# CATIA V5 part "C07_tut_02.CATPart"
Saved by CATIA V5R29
Part number: Part1
Bounding box of the stored display mesh (mm): x 0 to 32, y -32 to 32, z -15 to 36
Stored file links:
  D:\Abhinav\2019\3rd Session\CATIA V5 2019\RESOURCES\CATIA_RESOURCES\Tutorial Files\Tutorials\Tutorials\c07_catia_v5_6r2018_tut\c07_catia_v5_6r2018_tut\c07_catia_v5_6r2018_tut\C07_tut_02.CATPart
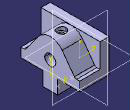
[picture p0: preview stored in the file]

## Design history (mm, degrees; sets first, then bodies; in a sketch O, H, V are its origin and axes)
Body1 (main body)
  Sketch1 on zx-plane, origin (0, 0, 0), H (-1, 0, 0), V (0, 0, 1)
    point P1 (0, 36)
    line L1 (0, 36) -> (0, 0)
    line L2 (0, 0) -> (-32, 0)
    line L3 (0, 36) -> (-10, 36)
    line L4 (-10, 36) -> (-10, 10)
    line L5 (-10, 10) -> (-32, 10)
    line L6 (-32, 10) -> (-32, 0)
    length L2 = 32
    length L3 = 10
    length L6 = 10
    distance L3 L2 = 36
    coincidence: P1 V
    vertical: L1 V, L4 V, L6 V
    horizontal: L2 H, L3 H, L5 H
  Pad1: profile Sketch1, direction (0, 1, 0), length 32, mirrored extent
  Sketch2 on face of Pad1 from Sketch1.L6, origin (32, 0, 0), H (0, 1, 0), V (0, 0, 1)
    arc A1 centre (0, 20) radius 16 from (12.9443, 29.4046) to (-12.9443, 29.4046) ccw
    point P1 (0, 20)
    reference projected line E1 (-32, 36) -> (32, 36) from edge [face of Pad1 from Sketch1.L4 | face of Pad1 from Sketch1.L3]
    line L1 (-27.0425, 10) -> (27.0425, 10)
    point P2 (-27.0425, 10)
    point P3 (27.0425, 10)
    reference projected line E2 (-32, 10) -> (32, 10) from edge [face of Pad1 from Sketch1.L6 | face of Pad1 from Sketch1.L5]
    line L2 (-27.0425, 10) -> (-12.9443, 29.4046)
    line L3 (27.0425, 10) -> (12.9443, 29.4046)
    radius A1 = 16
    angle L3 L2 = 72
    coincidence: P1 V, L1 E2
    tangency: A1 E1, L2 A1, L3 A1
    horizontal: L1 H
    symmetry: P3 P2 V
  Pad2: profile Sketch2, direction (1, 0, 0), up to the existing solid (limit type 2)
  Sketch3 on face of Pad2, origin (32, 0, 0), H (0, 1, 0), V (0, 0, 1)
    line L1 (-8, 0) -> (8, 0)
    line L2 (8, 0) -> (8, -15)
    line L3 (8, -15) -> (-8, -15)
    line L4 (-8, -15) -> (-8, 0)
    reference projected line E1 (-32, 0) -> (32, 0) from edge [face of Pad1 from Sketch1.L2 | face of Pad1 from Sketch1.L6]
    length L2 = 15
    length L3 = 16
    horizontal: L1 H, L3 H
    vertical: L2 V, L4 V
    symmetry: L2 L4 V
    coincidence: L1 E1
  Pad3: profile Sketch3, direction (1, 0, 0), up to face of Pad1 from Sketch1.L1
  Sketch4 on zx-plane, origin (0, 0, 0), H (-1, 0, 0), V (0, 0, 1)
    point P1 (-20, 36)
    reference projected line E1 (0, 36) -> (-10, 36) from edge [face of Pad1 from Sketch1.L3 | end face of Pad1]
    reference projected line E2 (0, 0) -> (0, 36) from edge [face of Pad1 from Sketch1.L1 | end face of Pad1]
    distance P1 E2 = 20
    coincidence: P1 E1
  Sketch5 on {plane type Tangent, Support face of Pad2 from Sketch2.A1, RefPoint Sketch4.P1}, origin (20, 0, 36), H (1, 0, 0), V (0, -1, 0)
    point P1 (0, 0)
    reference projected point E1 (0, 0) from Sketch4.P1
    coincidence: E1 P1
  Hole1: placed by Sketch5, at (20, 0, 36) direction (0, 0, -1), diameter 6, depth 16, V-bottom angle 120, counterbore diameter 10, counterbore depth 4
  Sketch6 on face of Pad2, origin (32, 0, 0), H (0, 1, 0), V (0, 0, 1)
    point P1 (0, 14)
    reference projected line E1 (-8, -15) -> (8, -15) from edge [face of Pad3 from Sketch3.L3 | start face of Pad3]
    distance P1 E1 = 29
    coincidence: P1 V
  Sketch7 on face of Pad2, origin (32, 0, 10), H (0, 1, 0), V (0, 0, 1)
    point P1 (0, 4)
    reference projected point E1 (0, 4) from Sketch6.P1
    coincidence: E1 P1
  Hole2: placed by Sketch7, at (32, 0, 14) direction (-1, 0, 0), diameter 12, depth 24
  Fillet1: radius 3, on edge [face of Pad1 from Sketch1.L5 | face of Pad2 from Sketch2.L3]; edge [face of Pad2 from Sketch2.L2 | face of Pad1 from Sketch1.L5]
  Sketch8 on zx-plane, origin (0, 0, 0), H (-1, 0, 0), V (0, 0, 1)
    point P1 (-24, -15)
    point P2 (-8, -15)
    reference projected line E1 (-32, -15) -> (0, -15) from edge [face of Pad3 from Sketch3.L3 | face of Pad3 from Sketch3.L2]
    reference projected line E2 (-32, -15) -> (0, -15) from edge [face of Pad3 from Sketch3.L3 | face of Pad3 from Sketch3.L2]
    reference projected line E3 (-32, -15) -> (-32, 0) from edge [face of Pad3 from Sketch3.L2 | face of Pad2]
    distance E3 P1 = 8
    distance P2 P1 = 16
    coincidence: P1 E1, P2 E2
  Sketch9 on face of Pad3 from Sketch3.L3, origin (8, 0, -15), H (1, 0, 0), V (0, -1, 0)
    point P1 (0, 0)
    reference projected point E1 (0, 0) from Sketch8.P2
    coincidence: E1 P1
  Hole3: placed by Sketch9, at (8, 0, -15) direction (0, 0, 1), diameter 6, depth 16, V-bottom angle 120
  Sketch10 on face of Pad3 from Sketch3.L3, origin (24, 0, -15), H (1, 0, 0), V (0, -1, 0)
    point P1 (0, 0)
    reference projected point E1 (0, 0) from Sketch8.P1
    coincidence: E1 P1
  Hole4: placed by Sketch10, at (24, 0, -15) direction (0, 0, 1), diameter 6, depth 16, V-bottom angle 120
